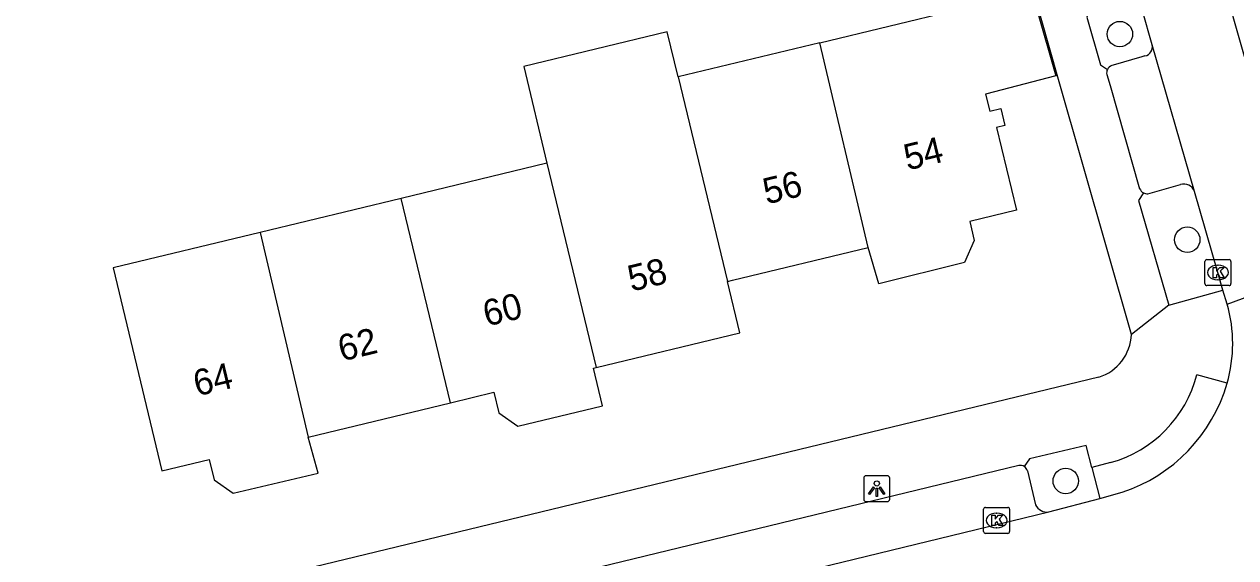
# Model space of a CAD drawing. Extents: x 159718 to 160783, y 383290 to 384030.
# Drawn here: x 160207.07 to 160253.65, y 383575.74 to 383596.25 of the extents above; entities that cross this region are included whole.
import ezdxf

# ---------------------------------------------------------------- set-up
doc = ezdxf.new("R2010")
doc.units = 0
for name, color, linetype in [('IMGEO_Boom', 7, 'Continuous'), ('IMGEO_Kolk', 7, 'Continuous'), ('IMGEO_Lichtpunt', 7, 'Continuous'), ('IMGEO_Pand', 7, 'Continuous'), ('IMGEO_Pand_nummerreeks', 7, 'Continuous'), ('IMGEO_Parkeervlak_open', 7, 'Continuous'), ('IMGEO_Rijbaan_lokaal_open', 7, 'Continuous'), ('IMGEO_Voetpad_open', 7, 'Continuous')]:
    doc.layers.add(name, color=color, linetype=linetype)

msp = doc.modelspace()

# ---------------------------------------------------------------- linework, layer by layer
at = {"layer": 'IMGEO_Boom'}
for centre in [(160249.196, 383595.872), (160251.786, 383587.968), (160247.114, 383578.694)]:
    msp.add_circle(centre, 0.489, dxfattribs=at)
at = {"layer": 'IMGEO_Kolk'}
for p, q in [((160252.464, 383586.279), (160252.464, 383587.131)), ((160252.539, 383587.205), (160253.391, 383587.205)), ((160253.465, 383587.131), (160253.465, 383586.279)), ((160252.952, 383586.985), (160252.977, 383586.985)), ((160253.391, 383586.205), (160252.539, 383586.205)), ((160252.975, 383586.425), (160252.95, 383586.425)), ((160244.032, 383577.679), (160244.884, 383577.679)), ((160243.957, 383576.753), (160243.957, 383577.605)), ((160244.445, 383577.459), (160244.47, 383577.459)), ((160244.958, 383577.605), (160244.958, 383576.753)), ((160244.468, 383576.899), (160244.443, 383576.899)), ((160244.884, 383576.679), (160244.032, 383576.679))]:
    msp.add_line(p, q, dxfattribs=at)
for points in [[(160252.464, 383586.279), (160252.464, 383587.131)], [(160252.539, 383587.205), (160253.391, 383587.205)], [(160253.465, 383587.131), (160253.465, 383586.279)], [(160252.785, 383586.905), (160252.908, 383586.905), (160252.908, 383586.754), (160253.038, 383586.905), (160253.202, 383586.905), (160253.056, 383586.754), (160253.209, 383586.505), (160253.057, 383586.505), (160252.972, 383586.669), (160252.908, 383586.602), (160252.908, 383586.505), (160252.785, 383586.505), (160252.785, 383586.905)], [(160253.391, 383586.205), (160252.539, 383586.205)], [(160244.032, 383577.679), (160244.884, 383577.679)], [(160243.957, 383576.753), (160243.957, 383577.605)], [(160244.278, 383577.379), (160244.401, 383577.379), (160244.401, 383577.228), (160244.531, 383577.379), (160244.695, 383577.379), (160244.549, 383577.228), (160244.702, 383576.979), (160244.55, 383576.979), (160244.465, 383577.143), (160244.401, 383577.076), (160244.401, 383576.979), (160244.278, 383576.979), (160244.278, 383577.379)], [(160244.958, 383577.605), (160244.958, 383576.753)], [(160244.884, 383576.679), (160244.032, 383576.679)]]:
    msp.add_lwpolyline(points, dxfattribs=at)
for centre, start, end in [((160252.541, 383587.129), 91.552, 178.448), ((160252.541, 383587.129), 91.552, 178.448), ((160253.389, 383587.129), 1.552, 88.448), ((160253.389, 383587.129), 1.552, 88.448), ((160252.541, 383586.281), 181.552, 268.448), ((160252.541, 383586.281), 181.552, 268.448), ((160253.389, 383586.281), 271.552, 358.448), ((160253.389, 383586.281), 271.552, 358.448), ((160244.034, 383577.603), 91.552, 178.448), ((160244.034, 383577.603), 91.552, 178.448), ((160244.882, 383577.603), 1.552, 88.448), ((160244.882, 383577.603), 1.552, 88.448), ((160244.034, 383576.755), 181.552, 268.448), ((160244.034, 383576.755), 181.552, 268.448), ((160244.882, 383576.755), 271.552, 358.448), ((160244.882, 383576.755), 271.552, 358.448)]:
    msp.add_arc(centre, 0.0765, start, end, dxfattribs=at)
for centre, major_axis, ratio, start_param, end_param in [((160252.951, 383586.705), (-0.387, 0.002), 0.722429, 4.712389, 7.853982), ((160252.976, 383586.705), (-0.39, 0.002), 0.717154, 1.570796, 4.712389), ((160244.444, 383577.179), (-0.387, 0.002), 0.722429, 4.712389, 7.853982), ((160244.469, 383577.179), (-0.39, 0.002), 0.717154, 1.570796, 4.712389)]:
    msp.add_ellipse(centre, major_axis=major_axis, ratio=ratio, start_param=start_param, end_param=end_param, dxfattribs=at)
at = {"layer": 'IMGEO_Lichtpunt'}
for p, q in [((160239.35, 383578.801), (160239.35, 383577.994)), ((160239.35, 383578.801), (160239.35, 383577.994)), ((160240.252, 383578.896), (160239.444, 383578.896)), ((160240.252, 383578.896), (160239.444, 383578.896)), ((160240.346, 383577.994), (160240.346, 383578.801)), ((160240.346, 383577.994), (160240.346, 383578.801)), ((160239.444, 383577.9), (160240.252, 383577.9)), ((160239.444, 383577.9), (160240.252, 383577.9))]:
    msp.add_line(p, q, dxfattribs=at)
for points in [[(160239.724, 383578.465), (160239.763, 383578.437), (160239.575, 383578.175), (160239.537, 383578.202), (160239.724, 383578.465)], [(160239.826, 383578.417), (160239.873, 383578.417), (160239.873, 383578.095), (160239.826, 383578.095), (160239.826, 383578.417)], [(160239.936, 383578.437), (160239.974, 383578.464), (160240.161, 383578.202), (160240.122, 383578.174), (160239.936, 383578.437)]]:
    msp.add_lwpolyline(points, dxfattribs=at)
msp.add_circle((160239.849, 383578.599), 0.0994, dxfattribs=at)
for centre, start, end in [((160239.444, 383578.801), 90, 180), ((160239.444, 383578.801), 90, 180), ((160240.252, 383578.801), 0, 90), ((160240.252, 383578.801), 0, 90), ((160239.444, 383577.994), 180, 270), ((160239.444, 383577.994), 180, 270), ((160240.252, 383577.994), 270, 0), ((160240.252, 383577.994), 270, 360)]:
    msp.add_arc(centre, 0.0946, start, end, dxfattribs=at)
at = {"layer": 'IMGEO_Pand'}
for points in [[(160237.657, 383595.534), (160242.961, 383596.813), (160242.539, 383598.562), (160243.347, 383598.827), (160245.27, 383599.376), (160246.73, 383594.262), (160244.035, 383593.563), (160244.192, 383592.911), (160244.619, 383593.015), (160244.777, 383592.364), (160244.446, 383592.284), (160245.222, 383589.101), (160243.422, 383588.662), (160243.6, 383587.933), (160243.222, 383587.092), (160239.929, 383586.272), (160239.518, 383587.669)], [(160232.214, 383594.222), (160231.796, 383595.954), (160226.275, 383594.623), (160227.171, 383590.906)], [(160237.657, 383595.534), (160232.214, 383594.222)], [(160239.518, 383587.669), (160237.657, 383595.534)], [(160232.214, 383594.222), (160234.109, 383586.366)], [(160227.171, 383590.906), (160221.561, 383589.554)], [(160227.171, 383590.906), (160229.066, 383583.052)], [(160221.561, 383589.554), (160216.146, 383588.248)], [(160223.457, 383581.7), (160221.561, 383589.554)], [(160216.146, 383588.248), (160210.496, 383586.886), (160212.366, 383579.08), (160214.188, 383579.516), (160214.375, 383578.74), (160215.109, 383578.228), (160218.37, 383579.001), (160217.983, 383580.38)], [(160216.146, 383588.248), (160217.983, 383580.38)], [(160234.109, 383586.366), (160234.297, 383586.411), (160239.518, 383587.669)], [(160229.066, 383583.052), (160234.587, 383584.383), (160234.109, 383586.366)], [(160223.457, 383581.7), (160225.129, 383582.103), (160225.32, 383581.316), (160226.051, 383580.803), (160229.307, 383581.588), (160228.96, 383583.026), (160229.066, 383583.052)], [(160217.983, 383580.38), (160223.457, 383581.7)]]:
    msp.add_lwpolyline(points, dxfattribs=at)
at = {"layer": 'IMGEO_Parkeervlak_open'}
for points in [[(160250.16, 383595.031), (160250.04, 383594.997), (160248.936, 383594.68), (160248.881, 383594.664)], [(160250.272, 383589.728), (160251.52, 383590.088)], [(160245.643, 383579.088), (160245.956, 383577.783)]]:
    msp.add_lwpolyline(points, dxfattribs=at)
for centre, radius, start, end in [((160250.083, 383595.388), 0.366, 282.1013, 11.9348), ((160249.004, 383594.367), 0.321, 112.5892, 153.0336), ((160251.658, 383589.676), 0.434, 20.0534, 108.5077), ((160250.268, 383590.076), 0.348, 241.8995, 270.6709), ((160245.371, 383579.009), 0.283, 16.1059, 57.7477), ((160246.389, 383577.969), 0.471, 203.2767, 279.8158)]:
    msp.add_arc(centre, radius, start, end, dxfattribs=at)
at = {"layer": 'IMGEO_Rijbaan_lokaal_open'}
for points in [[(160245.86, 383623.489), (160251.53, 383603.625), (160256.367, 383586.618)], [(160249.638, 383584.324), (160246.837, 383594.126), (160244.866, 383601.082), (160242.228, 383610.369)], [(160250.441, 383595.464), (160250.062, 383596.77), (160250.043, 383596.816)], [(160248.018, 383596.752), (160247.928, 383596.519), (160248.456, 383594.688), (160248.718, 383594.513)], [(160252.066, 383589.825), (160250.441, 383595.464)], [(160248.688, 383594.324), (160248.817, 383593.889), (160249.956, 383589.929)], [(160253.156, 383586.032), (160252.965, 383586.705), (160252.066, 383589.825)], [(160250.104, 383589.769), (160249.911, 383589.473), (160251.077, 383585.455)], [(160253.322, 383585.494), (160256.367, 383586.618)], [(160251.077, 383585.455), (160253.156, 383586.032)], [(160253.322, 383585.494), (160253.156, 383586.032)], [(160251.077, 383585.455), (160249.638, 383584.324)], [(160248.382, 383582.689), (160210.673, 383573.568), (160210.886, 383572.735), (160205.458, 383571.364), (160180.862, 383565.396)], [(160253.317, 383582.451), (160252.157, 383582.777)], [(160248.114, 383579.212), (160247.898, 383580.059), (160245.716, 383579.545), (160245.522, 383579.249)], [(160245.305, 383579.284), (160218.32, 383572.745)], [(160248.839, 383579.399), (160248.114, 383579.212)], [(160248.42, 383578.017), (160249.279, 383578.259)], [(160246.469, 383577.505), (160248.42, 383578.017)], [(160233.866, 383574.446), (160246.469, 383577.505)]]:
    msp.add_lwpolyline(points, dxfattribs=at)
for centre, radius, start, end in [((160248.993, 383594.372), 0.309, 152.9202, 189.0411), ((160250.27, 383590.071), 0.344, 204.3264, 241.2112), ((160248.032, 383583.981), 5.502, 343.8514, 15.9603), ((160247.866, 383584.385), 1.773, 286.9142, 358.0232), ((160247.549, 383583.985), 4.764, 285.7118, 345.315), ((160247.331, 383584.176), 6.23, 288.2221, 343.9219), ((160245.373, 383579.016), 0.277, 57.427, 104.2483)]:
    msp.add_arc(centre, radius, start, end, dxfattribs=at)
at = {"layer": 'IMGEO_Voetpad_open'}
msp.add_lwpolyline([(160248.114, 383579.212), (160248.42, 383578.017)], dxfattribs=at)

# ---------------------------------------------------------------- texts
at = {"layer": 'IMGEO_Pand_nummerreeks'}
for s, rotation, p in [('54', 13.5505, (160241.027, 383590.626)), ('56', 13.5505, (160235.611, 383589.32)), ('58', 13.5505, (160230.414, 383585.969)), ('60', 13.5531, (160224.848, 383584.627)), ('62', 13.5531, (160219.276, 383583.284)), ('64', 13.5505, (160213.713, 383581.943))]:
    msp.add_text(s, height=1, rotation=rotation, dxfattribs=at).set_placement(p)

doc.saveas('drawing.dxf')
